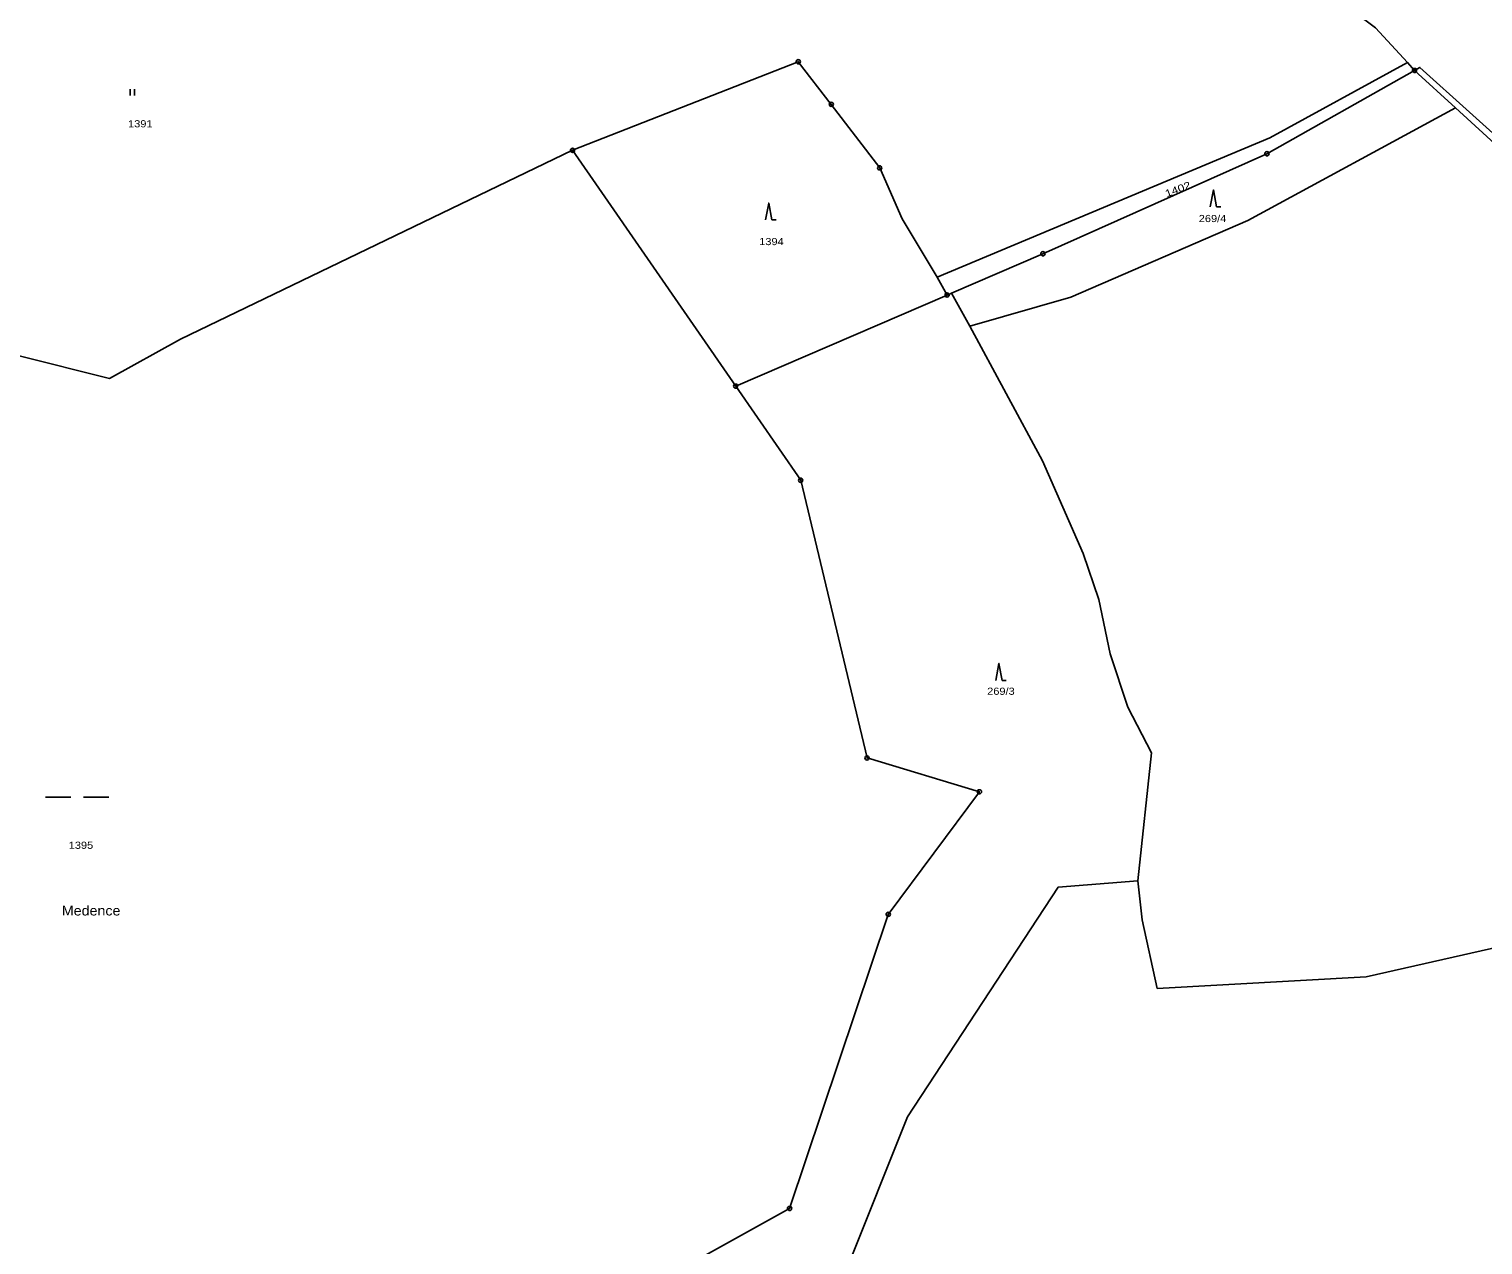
# Model space of a CAD drawing. Extents: x -872229 to -869198, y -1075981 to -1074329.
# Drawn here: x -870040 to -869694.9, y -1074938.2 to -1074649.5 of the extents above; entities that cross this region are included whole.
import ezdxf

# ---------------------------------------------------------------- set-up
doc = ezdxf.new("R2010")
doc.units = 0
doc.header["$LTSCALE"] = 0.68
for name, color, linetype, lineweight in [('1', 7, 'Continuous', 25), ('3', 7, 'Continuous', 25), ('7', 7, 'Continuous', 13), ('8', 7, 'Continuous', 25)]:
    doc.layers.add(name, color=color, linetype=linetype, lineweight=lineweight)
doc.layers.add('2', color=7, linetype='Continuous')

msp = doc.modelspace()

# ---------------------------------------------------------------- linework, layer by layer
at = {"layer": '1'}
for p, q in [((-869711.15, -1074659.32), (-869712.84, -1074657.47)), ((-869711.15, -1074659.32), (-869701.44, -1074668.21)), ((-869822.1, -1074712.65), (-869821.07, -1074712.21)), ((-869816.71, -1074720.02), (-869821.07, -1074712.21))]:
    msp.add_line(p, q, dxfattribs=at)
for points in [[(-869712.84, -1074657.47), (-869720.42, -1074649.17), (-869729.76, -1074642.12), (-869739.64, -1074635.61), (-869753.88, -1074626.92), (-869770.54, -1074620.9), (-869785.96, -1074613.96), (-869793.12, -1074610.67)], [(-869911.02, -1074678.28), (-869857.44, -1074657.25), (-869849.59, -1074667.37), (-869838.11, -1074682.45), (-869832.76, -1074694.54), (-869824.49, -1074708.42)], [(-869824.49, -1074708.42), (-869745.46, -1074675.33), (-869712.84, -1074657.47)], [(-869821.07, -1074712.21), (-869799.36, -1074702.85), (-869746.19, -1074679.1), (-869711.15, -1074659.32)], [(-869453.23, -1074793.29), (-869497.35, -1074770.43), (-869502.91, -1074766.99), (-869516.66, -1074755.78), (-869542.23, -1074736.35), (-869569.01, -1074723.84), (-869589.32, -1074714.31), (-869627.88, -1074704.89), (-869644.84, -1074704.23), (-869686.29, -1074679.82), (-869709.86, -1074658.59), (-869711.15, -1074659.32)], [(-869701.44, -1074668.21), (-869750.73, -1074694.98), (-869792.75, -1074713.16), (-869816.71, -1074720.02)], [(-869453.66, -1074794.85), (-869498.36, -1074771.77), (-869503.98, -1074768.2), (-869517.76, -1074757.22), (-869525.6, -1074751.31), (-869543.02, -1074738.02), (-869569.82, -1074725.31), (-869590.03, -1074715.95), (-869627.87, -1074706.45), (-869644.88, -1074705.89), (-869687.49, -1074680.97), (-869701.44, -1074668.21)], [(-870044.43, -1074699.07), (-870042.4, -1074727.1), (-870020.9, -1074732.51), (-870004.05, -1074723.11), (-869911.02, -1074678.28)], [(-869911.02, -1074678.28), (-869904.1, -1074688.29), (-869872.29, -1074734.28), (-869822.1, -1074712.65), (-869824.49, -1074708.42)], [(-869816.71, -1074720.02), (-869799.47, -1074751.99), (-869789.82, -1074774.02), (-869786.11, -1074784.95), (-869783.39, -1074797.89), (-869779.19, -1074810.5), (-869773.55, -1074821.33), (-869776.86, -1074851.73)], [(-869929.31, -1074968.38), (-869859.5, -1074929.56), (-869836.07, -1074859.72), (-869814.43, -1074830.62), (-869841.11, -1074822.59), (-869856.86, -1074756.63), (-869872.29, -1074734.28)], [(-869397.27, -1074865.36), (-869448.98, -1074844.13), (-869486.01, -1074834.03), (-869531.78, -1074827.54), (-869564.41, -1074831.36), (-869550.14, -1074861.73), (-869603.53, -1074857.64), (-869652.94, -1074860.42), (-869683.77, -1074865.74), (-869722.65, -1074874.59), (-869772.21, -1074877.32), (-869775.77, -1074861.05), (-869776.86, -1074851.73)], [(-869776.86, -1074851.73), (-869795.77, -1074853.27), (-869831.49, -1074907.84), (-869845.83, -1074943.67), (-869929.31, -1074968.38)]]:
    msp.add_lwpolyline(points, dxfattribs=at)
at = {"layer": '3'}
for p, q in [((-870016.021, -1074665.24), (-870016.021, -1074663.74)), ((-870015.02, -1074665.24), (-870015.02, -1074663.74)), ((-869758.12, -1074691.67), (-869757.124, -1074691.67)), ((-869863.69, -1074694.81), (-869862.694, -1074694.81)), ((-869809.05, -1074804.15), (-869808.054, -1074804.15)), ((-870036.119, -1074831.92), (-870030.119, -1074831.92)), ((-870027.119, -1074831.92), (-870021.119, -1074831.92))]:
    msp.add_line(p, q, dxfattribs=at)
for points in [[(-869863.69, -1074694.81), (-869864.44, -1074690.81), (-869865.19, -1074694.81)], [(-869758.12, -1074691.67), (-869758.87, -1074687.67), (-869759.62, -1074691.67)], [(-869809.05, -1074804.15), (-869809.8, -1074800.15), (-869810.55, -1074804.15)]]:
    msp.add_lwpolyline(points, dxfattribs=at)
at = {"layer": '8'}
for centre, radius in [((-869857.44, -1074657.2499), 0.5), ((-869857.44, -1074657.2499), 0.0303), ((-869711.15, -1074659.3199), 0.5), ((-869711.15, -1074659.3199), 0.0303), ((-869849.59, -1074667.3699), 0.5), ((-869849.59, -1074667.3699), 0.0303), ((-869911.02, -1074678.2799), 0.5), ((-869911.02, -1074678.2799), 0.0303), ((-869746.19, -1074679.0999), 0.5), ((-869746.19, -1074679.0999), 0.0303), ((-869838.11, -1074682.4499), 0.5), ((-869838.11, -1074682.4499), 0.0303), ((-869799.36, -1074702.8499), 0.5), ((-869799.36, -1074702.8499), 0.0303), ((-869822.1, -1074712.6499), 0.5), ((-869822.1, -1074712.6499), 0.0303), ((-869872.29, -1074734.2799), 0.5), ((-869872.29, -1074734.2799), 0.0303), ((-869856.86, -1074756.6299), 0.5), ((-869856.86, -1074756.6299), 0.0303), ((-869841.11, -1074822.5899), 0.5), ((-869841.11, -1074822.5899), 0.0303), ((-869814.43, -1074830.6199), 0.5), ((-869814.43, -1074830.6199), 0.0303), ((-869836.07, -1074859.7199), 0.5), ((-869836.07, -1074859.7199), 0.0303), ((-869859.5, -1074929.5599), 0.5), ((-869859.5, -1074929.5599), 0.0303)]:
    msp.add_circle(centre, radius, dxfattribs=at)

# ---------------------------------------------------------------- texts
at = {"layer": '2', "width": 1.15}
for s, p in [('1391', (-870016.53, -1074672.83)), ('269/4', (-869762.37, -1074695.33)), ('1394', (-869866.71, -1074700.8)), ('269/3', (-869812.6, -1074807.59)), ('1395', (-870030.62, -1074844.16))]:
    msp.add_text(s, height=1.7, dxfattribs=at).set_placement(p)
at = {"layer": '2', "width": 1.25}
msp.add_text('1402', height=1.7, rotation=21, dxfattribs=at).set_placement((-869769.965, -1074689.443))
at = {"layer": '7', "width": 1.1}
msp.add_text('Medence', height=2.3, dxfattribs=at).set_placement((-870032.25, -1074859.99))

doc.saveas('drawing.dxf')
